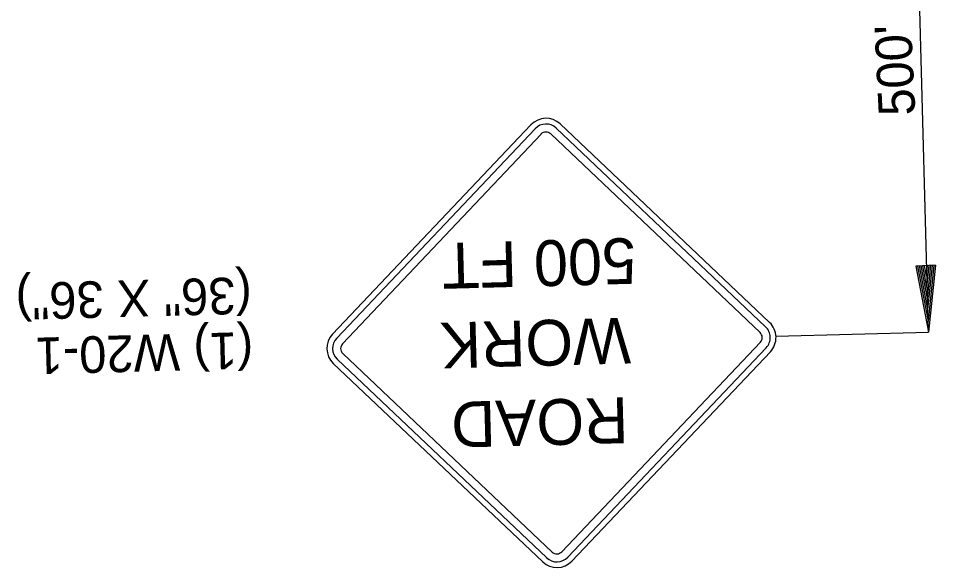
# Model space of a CAD drawing. Extents: x 1929653 to 1931621, y 596452 to 600944.
# Drawn here: x 1930637.6 to 1930787.9, y 600549.2 to 600639.1 of the extents above; entities that cross this region are included whole.
import ezdxf

# ---------------------------------------------------------------- set-up
doc = ezdxf.new("R2010")
doc.units = 0
for name, color, linetype in [('P_TC_Signs_Temporary', 7, 'Continuous'), ('R_Border', 7, 'Continuous'), ('R_Draft', 7, 'Continuous')]:
    doc.layers.add(name, color=color, linetype=linetype)

msp = doc.modelspace()

# ---------------------------------------------------------------- linework, layer by layer
at = {"layer": 'P_TC_Signs_Temporary'}
for p, q in [((1930689.08, 600587.39), (1930721.58, 600621.68)), ((1930689.76, 600586.74), (1930722.26, 600621.04)), ((1930725.71, 600621.13), (1930760, 600588.63)), ((1930726.35, 600621.81), (1930760.65, 600589.31)), ((1930690.71, 600585.84), (1930723.22, 600620.14)), ((1930724.81, 600620.18), (1930759.1, 600587.68)), ((1930759.14, 600586.09), (1930726.64, 600551.79)), ((1930760.1, 600585.18), (1930727.59, 600550.89)), ((1930725.05, 600551.75), (1930690.76, 600584.25)), ((1930760.78, 600584.54), (1930728.27, 600550.24)), ((1930723.5, 600550.12), (1930689.21, 600582.62)), ((1930724.15, 600550.8), (1930689.85, 600583.3))]:
    msp.add_line(p, q, dxfattribs=at)
for centre, radius, start, end in [((1930724.03, 600619.36), 3.38, 46.5377, 136.5377), ((1930724.03, 600619.36), 2.44, 46.5377, 136.5377), ((1930724.03, 600619.36), 1.13, 46.5377, 136.5377), ((1930758.33, 600586.86), 2.44, 316.5377, 46.5377), ((1930758.33, 600586.86), 3.38, 316.5377, 46.5377), ((1930691.53, 600585.07), 3.38, 136.5377, 226.5377), ((1930691.53, 600585.07), 2.44, 136.5377, 226.5377), ((1930758.33, 600586.86), 1.12, 316.5377, 46.5377), ((1930691.53, 600585.07), 1.12, 136.5377, 226.5377), ((1930725.82, 600552.57), 2.44, 226.5377, 316.5377), ((1930725.82, 600552.57), 1.13, 226.5377, 316.5377), ((1930725.82, 600552.57), 3.37, 226.5377, 316.5377)]:
    msp.add_arc(centre, radius, start, end, dxfattribs=at)
at = {"layer": 'R_Draft'}
for p, q in [((1930786.69, 600587.74), (1930784.01, 600687.71)), ((1930787.85, 600598.68), (1930784.59, 600598.55)), ((1930784.59, 600598.55), (1930786.69, 600587.74)), ((1930784.86, 600598.56), (1930786.61, 600589.56)), ((1930785.14, 600598.57), (1930786.53, 600591.43)), ((1930785.41, 600598.58), (1930786.45, 600593.24)), ((1930785.69, 600598.59), (1930786.37, 600595.08)), ((1930785.97, 600598.61), (1930786.29, 600596.9)), ((1930786.48, 600598.62), (1930786.29, 600596.9)), ((1930786.75, 600598.64), (1930786.37, 600595.08)), ((1930787.03, 600598.65), (1930786.45, 600593.24)), ((1930787.3, 600598.66), (1930786.53, 600591.43)), ((1930787.58, 600598.67), (1930786.61, 600589.56)), ((1930787.85, 600598.68), (1930786.69, 600587.74)), ((1930761.7, 600587.07), (1930786.69, 600587.74))]:
    msp.add_line(p, q, dxfattribs=at)

# ---------------------------------------------------------------- texts
at = {"layer": 'P_TC_Signs_Temporary'}
for s, p in [('500 FT ', (1930738.68, 600603.17)), ('WORK', (1930737.81, 600590.12)), (' ROAD ', (1930740.19, 600577.16))]:
    msp.add_text(s, height=7.5, rotation=181.5377, dxfattribs=at).set_placement(p)
at = {"layer": 'R_Border'}
for s, p in [('(36" X 36")', (1930675.79, 600596.77)), ('(1) W20-1', (1930676.03, 600587.78))]:
    msp.add_text(s, height=6, rotation=181.5377, dxfattribs=at).set_placement(p)
at = {"layer": 'R_Draft'}
msp.add_text("500'", height=6, rotation=92.7681, dxfattribs=at).set_placement((1930784.54, 600623.29))

doc.saveas('drawing.dxf')
